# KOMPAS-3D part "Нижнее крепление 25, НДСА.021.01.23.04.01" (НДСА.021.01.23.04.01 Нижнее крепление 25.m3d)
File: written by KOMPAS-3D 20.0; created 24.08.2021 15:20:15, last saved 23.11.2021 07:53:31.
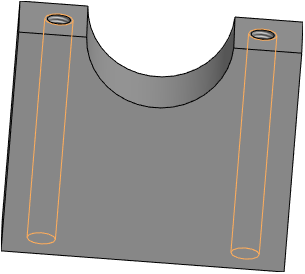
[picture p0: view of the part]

Document properties: Полное имя файла: C:\Users\s.pischagina\Desktop\PLM\НДСА.021.01.23.04.01 Нижнее крепление 25.m3d

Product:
- Part/product: Нижнее крепление 25  | designation НДСА.021.01.23.04.01
    Материал: АМг6  ГОСТ 4784-2019 (density 2640 kg/m3)
    Масса: 0.065326
    additional columns: <item xmlns="http://appius.ru/pdm" xmlns:xs="http://www.w3.org/2001/XMLSchema" x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; <item xmlns="http://appius.ru/pdm" xmlns:xs="http://www.w3.org/2001/XMLSchema" x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; <item xmlns="http://appius.ru/pdm" xmlns:xs="http://www.w3.org/2001/XMLSchema" x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; <item xmlns="http://appius.ru/pdm" xmlns:xs="http://www.w3.org/2001/XMLSchema" x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; <item xmlns="http://appius.ru/pdm" xmlns:xs="http://www.w3.org/2001/XMLSchema" x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
    source file: НДСА.021.01.23.04.01 Нижнее крепление 25.cdw

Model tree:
1. Эскиз:1
2. Элемент выдавливания:1
     Расстояние 1 = 70
3. Эскиз:2  (with: Элемент выдавливания:1)
4. Элемент выдавливания:2
     Расстояние 2 = 107
5. Эскиз:3  (with: Элемент выдавливания:1, Элемент выдавливания:2)
6. Элемент выдавливания:3
     Расстояние 2 = 14
7. Эскиз:4  (with: Элемент выдавливания:3)
8. Элемент выдавливания:6
     Расстояние 1 = 17.99
9. Эскиз:5  (with: Элемент выдавливания:1)
10. Эскиз:6  (with: Элемент выдавливания:1)
11. Элемент выдавливания:7  (with: Элемент выдавливания:1)
     Расстояние 2 = 10
12. Эскиз:7  (with: Элемент выдавливания:7)
13. Элемент выдавливания:8
14. Условное изображение резьбы:6  (with: Элемент выдавливания:8)  (labels: M5; cil0_24705-2004 coarse)
     Длина резьбы = 42.01; Шаг резьбы = 0.8; Номинальный диаметр резьбы = 5
15. Подгонка:6  (with: Элемент выдавливания:8)
16. Условное изображение резьбы:7  (with: Элемент выдавливания:8)  (labels: M5; cil0_24705-2004 coarse)
     Длина резьбы = 42.01; Шаг резьбы = 0.8; Номинальный диаметр резьбы = 5
17. Подгонка:7  (with: Элемент выдавливания:8)  (labels: АМг6  ГОСТ 4784-2019)

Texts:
  НДСА.021.01.23.04.01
